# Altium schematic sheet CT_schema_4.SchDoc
size 334 x 183 mm
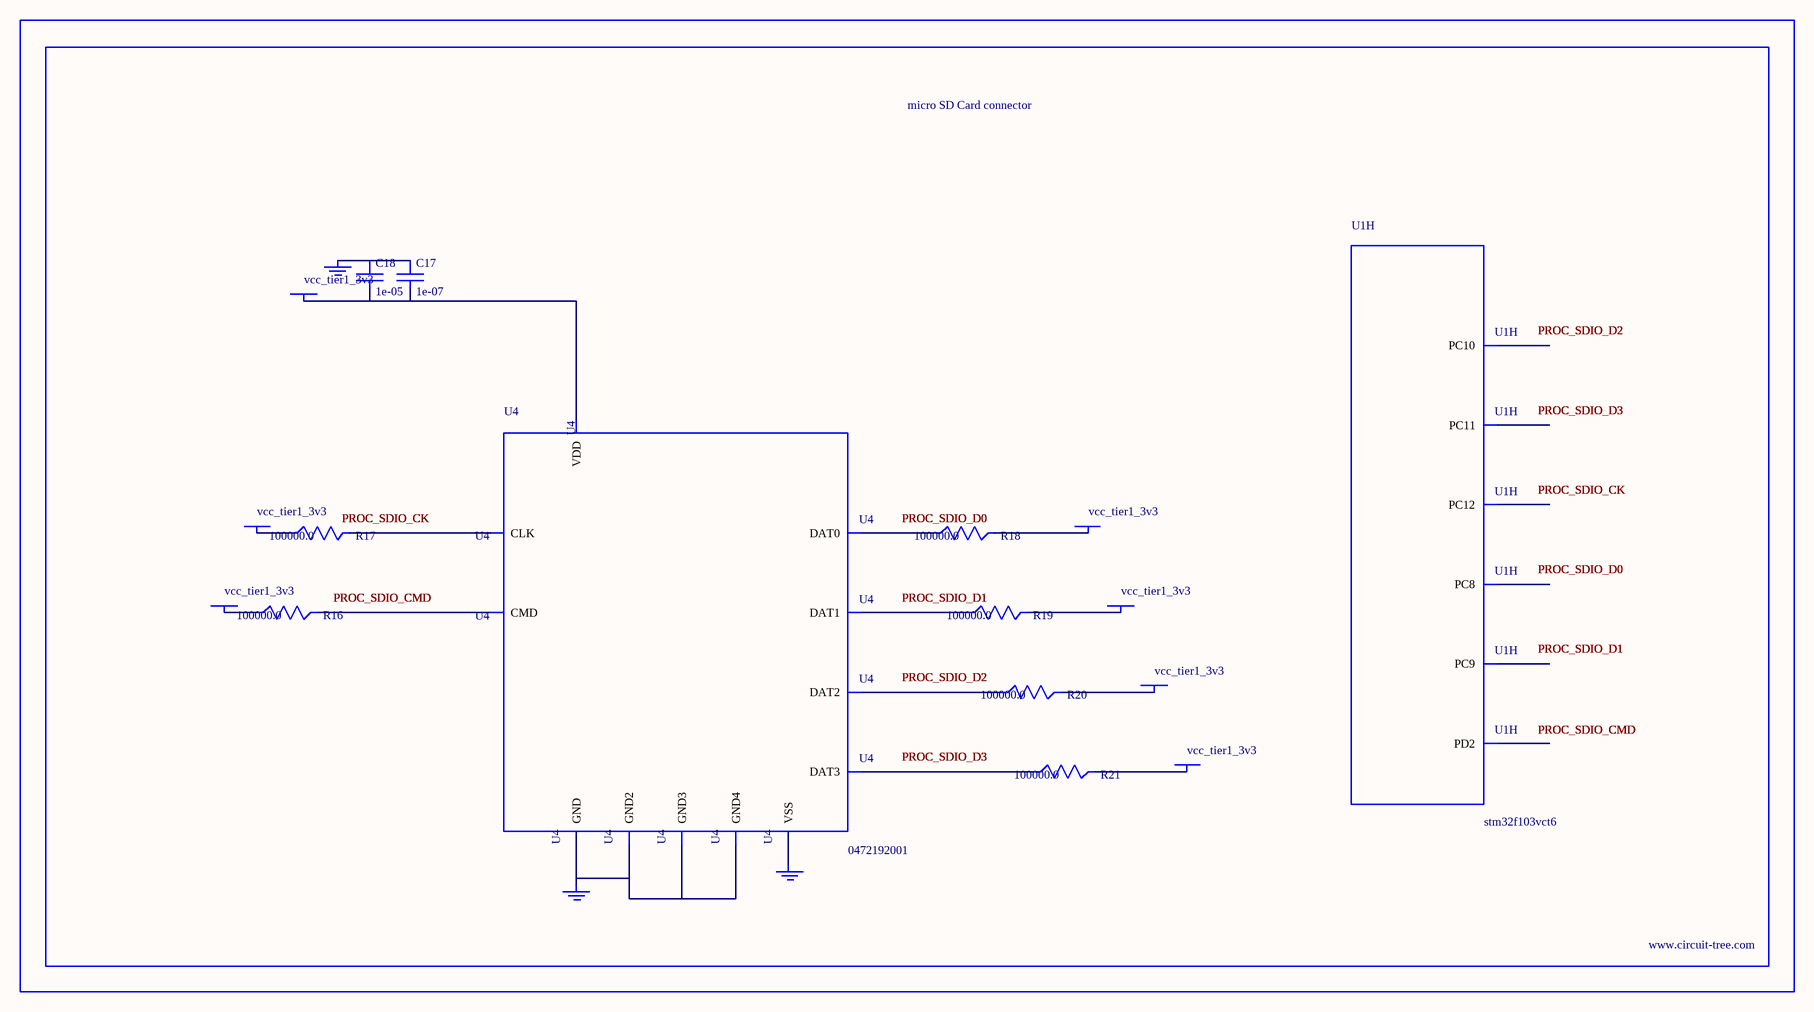
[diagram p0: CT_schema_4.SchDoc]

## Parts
BORDER3  (no value)
C17  1e-07  [C0402]
C18  1e-05  [C0805]
GND_INSTANCE_3_0  (no value)
GND_INSTANCE_3_1  (no value)
GND_INSTANCE_3_2  (no value)
POWER_INSTANCE_3_0  vcc_tier1_3v3
POWER_INSTANCE_3_1  vcc_tier1_3v3
POWER_INSTANCE_3_2  vcc_tier1_3v3
POWER_INSTANCE_3_3  vcc_tier1_3v3
POWER_INSTANCE_3_4  vcc_tier1_3v3
POWER_INSTANCE_3_5  vcc_tier1_3v3
POWER_INSTANCE_3_6  vcc_tier1_3v3
R16  100000.0  [R0603]
R17  100000.0  [R0603]
R18  100000.0  [R0603]
R19  100000.0  [R0603]
R20  100000.0  [R0603]
R21  100000.0  [R0603]
U1  stm32f103vct6  [LQFP100]  (part H of 10)
U4  0472192001  [MOLEX_47219-2001]

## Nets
NetC17_1: C17.1 C18.1 GND_INSTANCE_3_0.0(GND)
NetC17_2: C17.2 C18.2 POWER_INSTANCE_3_3.0(PWR) U4.4(VDD)
NetGND_INSTANCE_3_1_0: GND_INSTANCE_3_1.0(GND) U4.6(VSS)
NetGND_INSTANCE_3_2_0: GND_INSTANCE_3_2.0(GND) U4.G1(GND) U4.G2(GND2) U4.G3(GND3) U4.G4(GND4)
NetPOWER_INSTANCE_3_0_0: POWER_INSTANCE_3_0.0(PWR) R20.2
NetPOWER_INSTANCE_3_1_0: POWER_INSTANCE_3_1.0(PWR) R21.2
NetPOWER_INSTANCE_3_2_0: POWER_INSTANCE_3_2.0(PWR) R16.1
NetPOWER_INSTANCE_3_4_0: POWER_INSTANCE_3_4.0(PWR) R17.1
NetPOWER_INSTANCE_3_5_0: POWER_INSTANCE_3_5.0(PWR) R18.2
NetPOWER_INSTANCE_3_6_0: POWER_INSTANCE_3_6.0(PWR) R19.2
NetR16_2: R16.2 U4.3(CMD)
NetR17_2: R17.2 U4.5(CLK)
NetR18_1: R18.1 U4.7(DAT0)
NetR19_1: R19.1 U4.8(DAT1)
NetR20_1: R20.1 U4.1(DAT2)
NetR21_1: R21.1 U4.2(DAT3)

Not connected (* = marked no-connect by the designer): U1 65(PC8) 66(PC9) 78(PC10) 79(PC11) 80(PC12) 83(PD2)

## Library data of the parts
BORDER3 = BORDER_PAGE3
C17 = C0402C104K3RACTU
C18 = C0805C106K8RACTU
GND_INSTANCE_3_0-GND_INSTANCE_3_2 = GND
POWER_INSTANCE_3_0-POWER_INSTANCE_3_6 = PWR
R16-R21 = RC0603JR-07100KL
